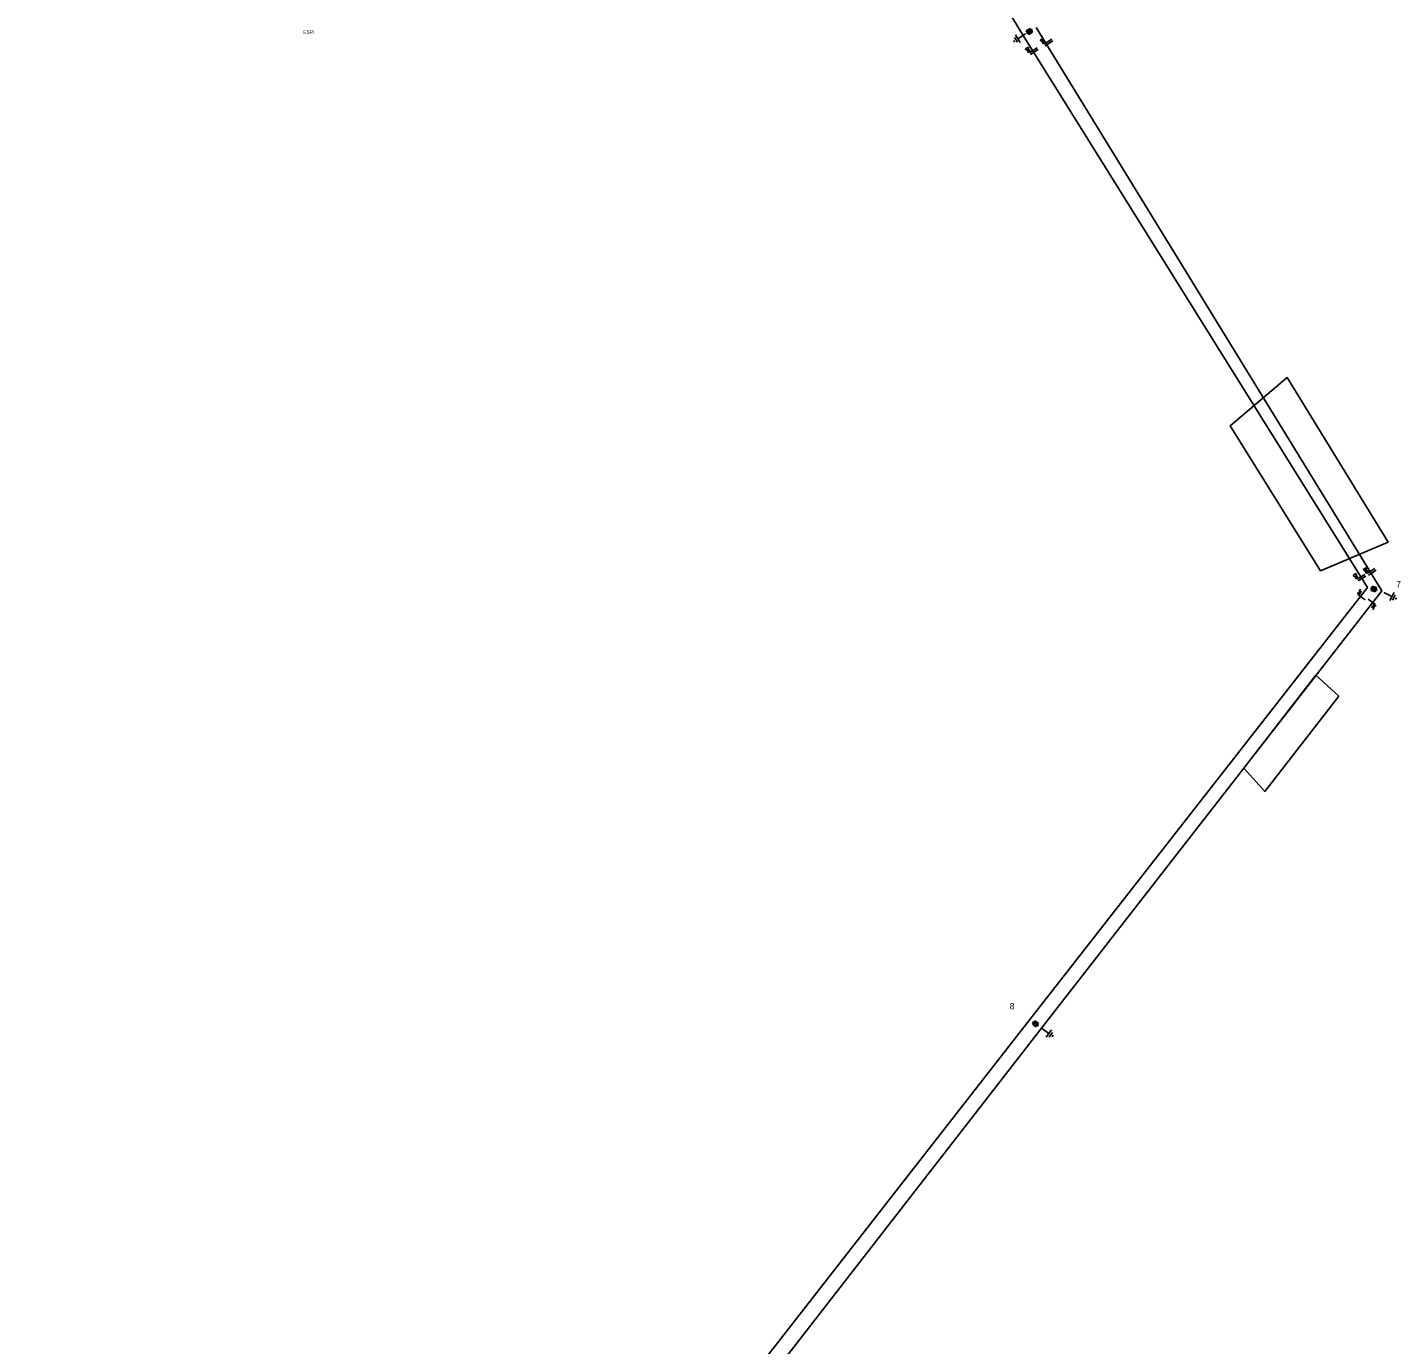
# Model space of a CAD drawing. Extents: x -788491 to -785797, y -1154753 to -1152002.
# Drawn here: x -787571.6 to -787193.3, y -1154362.4 to -1153999.5 of the extents above; entities that cross this region are included whole.
import ezdxf

# ---------------------------------------------------------------- set-up
doc = ezdxf.new("R2010")
doc.units = 0
for name, color, linetype in [('Vrstva 1', 7, 'Continuous'), ('Vrstva 13', 7, 'Continuous'), ('Vrstva 14', 7, 'Continuous'), ('Vrstva 15', 7, 'Continuous'), ('Vrstva 18', 7, 'Continuous'), ('Vrstva 2', 7, 'Continuous'), ('Vrstva 27', 7, 'Continuous'), ('Vrstva 35', 7, 'Continuous')]:
    doc.layers.add(name, color=color, linetype=linetype)

# ---------------------------------------------------------------- blocks, each defined once
blk = doc.blocks.new('VN850')
at = {"layer": 'Vrstva 15'}
for points in [[(-0.56, 1.43), (-0.56, -1.07)], [(-0.01, 1.43), (-0.01, -1.07)], [(-2.09, -0.54), (-1.78, -0.54)], [(-2.09, -1.41), (-2.09, -0.54)], [(-1.78, -1.41), (-2.09, -1.41)], [(-1.78, -0.54), (-1.66, -0.6)], [(-1.67, -1.35), (-1.78, -1.41)], [(-1.59, -1.2), (-1.67, -1.35)], [(-1.66, -0.6), (-1.59, -0.75)], [(-1.59, -0.75), (-1.55, -0.96)], [(-1.55, -0.96), (-1.59, -1.2)], [(-1.26, -0.54), (-1.26, -1.41)], [(-0.85, -0.54), (-1.26, -1.09)], [(-1.13, -0.92), (-0.77, -1.41)]]:
    blk.add_lwpolyline(points, dxfattribs=at)
blk = doc.blocks.new('VN840')
at = {"layer": 'Vrstva 15'}
for points in [[(-0.01, 1.41), (-0.01, -1.09)], [(-1.51, -1.24), (-1.51, -1.15)], [(-1.48, -1.35), (-1.51, -1.24)], [(-1.33, -1.42), (-1.48, -1.35)], [(-1.27, -1.42), (-1.33, -1.42)], [(-1.13, -1.35), (-1.27, -1.42)], [(-1.09, -1.24), (-1.13, -1.35)], [(-1.09, -0.59), (-1.09, -1.24)], [(-0.68, -0.59), (-0.68, -1.42)], [(-0.68, -1.11), (-0.27, -0.59)], [(-0.54, -0.94), (-0.2, -1.42)]]:
    blk.add_lwpolyline(points, dxfattribs=at)
blk = doc.blocks.new('VN810')
at = {"layer": 'Vrstva 14'}
for points in [[(1.25, -3.75), (-1.25, -3.75)], [(0, -1.25), (0, -3.75)], [(0.77, -4.37), (-0.8, -4.37)], [(0, -5), (-0.25, -5)], [(0.27, -5), (0, -5)]]:
    blk.add_lwpolyline(points, dxfattribs=at)
blk = doc.blocks.new('VN470')
at = {"layer": 'Vrstva 2'}
for points in [[(-1.23, 1.22), (1.23, 1.22)], [(-1.23, -1.23), (-1.23, 1.22)], [(-0.92, 0.9), (0.92, 0.9)], [(-0.92, -0.95), (-0.92, 0.9)], [(-0.61, 0.61), (0.61, 0.61)], [(-0.61, -0.62), (-0.61, 0.61)], [(-0.31, -0.27), (-0.31, 0.34)], [(-0.31, 0.34), (0.31, 0.34)], [(0, 1.22), (0, 1.97)], [(0.31, 0.34), (0.31, -0.27)], [(0.61, 0.61), (0.61, -0.62)], [(0.92, 0.9), (0.92, -0.95)], [(1.23, 1.22), (1.23, -1.23)], [(1.23, -1.23), (-1.23, -1.23)], [(0.92, -0.95), (-0.92, -0.95)], [(0.61, -0.62), (-0.61, -0.62)], [(0.31, -0.27), (-0.31, -0.27)], [(0, -1.23), (0, -1.98)]]:
    blk.add_lwpolyline(points, dxfattribs=at)

msp = doc.modelspace()

# ---------------------------------------------------------------- linework, layer by layer
at = {"layer": 'Vrstva 1'}
for points in [[(-787297.28, -1154001.71), (-787347.42, -1153919.07), (-787418.52, -1153804.59)], [(-787642.19, -1154725.26), (-787585.43, -1154652.32), (-787493.57, -1154533.63), (-787391.24, -1154402.66), (-787292.22, -1154275.24), (-787198.47, -1154154.71), (-787293.67, -1153999.52)], [(-787647.19, -1154724.52), (-787589.09, -1154649.65), (-787497.04, -1154530.83), (-787394.48, -1154399.84), (-787295.42, -1154272.85), (-787202.42, -1154153.82), (-787297.28, -1154001.71)]]:
    msp.add_lwpolyline(points, dxfattribs=at)
at = {"layer": 'Vrstva 35'}
for points in [[(-787196.7, -1154141.34), (-787215.33, -1154149.18), (-787240.23, -1154109.26), (-787224.56, -1154095.94)], [(-787210.29, -1154183.74), (-787230.71, -1154209.99), (-787236.5, -1154203.59), (-787216.59, -1154178)]]:
    msp.add_lwpolyline(points, close=True, dxfattribs=at)

# ---------------------------------------------------------------- block references
at = {"layer": 'Vrstva 13'}
for p, xscale, yscale, rotation in [((-787295.54, -1154000.62), 0.5, 0.5, -57.54109446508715), ((-787200.62, -1154154.24), 0.49999999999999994, 0.5000000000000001, 75.77451387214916), ((-787293.85, -1154274.03), 0.5000000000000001, 0.5000000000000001, 53.1701388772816)]:
    msp.add_blockref('VN470', p, dxfattribs=dict(at, xscale=xscale, yscale=yscale, rotation=rotation))
at = {"layer": 'Vrstva 15'}
for p, rotation in [((-787295.54, -1154000.62), -57.56061941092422), ((-787198.98, -1154154.6), 62.7055444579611), ((-787293.2, -1154274.48), 54.1682416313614)]:
    msp.add_blockref('VN810', p, dxfattribs=dict(at, rotation=rotation))
at = {"layer": 'Vrstva 18'}
for name, p, rotation in [('VN850', (-787294.33, -1154006.4), -57.54109164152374), ('VN850', (-787290.26, -1154003.99), -57.52790006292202), ('VN850', (-787201.24, -1154149.83), -57.52790000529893), ('VN850', (-787204.02, -1154151.44), -57.541180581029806), ('VN840', (-787204.18, -1154156.37), -126.8298611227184), ('VN840', (-787201.06, -1154157.87), 53.170280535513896)]:
    msp.add_blockref(name, p, dxfattribs=dict(at, rotation=rotation))

# ---------------------------------------------------------------- texts
at = {"layer": 'Vrstva 14'}
for s, p in [('7', (-787194.47, -1154153.76)), ('8', (-787300.96, -1154270.04))]:
    msp.add_text(s, height=1.75, dxfattribs=at).set_placement(p)
at = {"layer": 'Vrstva 27'}
msp.add_text('ESPI', height=1, dxfattribs=at).set_placement((-787495.64, -1154001.3))

doc.saveas('drawing.dxf')
